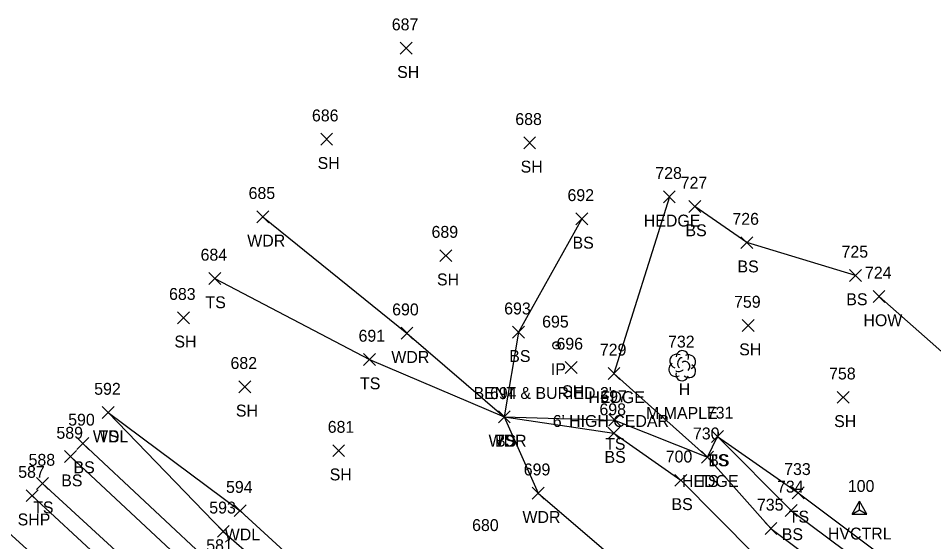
# Model space of a CAD drawing. Extents: x 1611034 to 1613847, y 761049 to 763902.
# Drawn here: x 1611761.1 to 1611914.9, y 763188 to 763276 of the extents above; entities that cross this region are included whole.
import ezdxf

# ---------------------------------------------------------------- set-up
doc = ezdxf.new("R2010")
doc.units = 0
for name, color, linetype in [('C_A', 7, 'Continuous'), ('C_I', 7, 'Continuous'), ('CPSM', 7, 'Continuous'), ('L_A', 7, 'Continuous'), ('L_C', 7, 'Continuous'), ('L_I', 7, 'Continuous'), ('L_TIC', 7, 'Continuous'), ('LAHR', 7, 'Continuous'), ('LAWA', 7, 'Continuous'), ('LBC', 7, 'Continuous'), ('LELB', 7, 'Continuous'), ('LTD', 7, 'Continuous'), ('M_A', 7, 'Continuous'), ('M_C', 7, 'Continuous'), ('M_I', 7, 'Continuous'), ('MPIR', 7, 'Continuous'), ('P_A', 7, 'Continuous'), ('P_I', 7, 'Continuous'), ('P_TIC', 7, 'Continuous'), ('PET', 7, 'Continuous'), ('PSP', 7, 'Continuous')]:
    doc.layers.add(name, color=color, linetype=linetype)

msp = doc.modelspace()

# ---------------------------------------------------------------- linework, layer by layer
at = {"layer": 'CPSM'}
for p, q in [((1611901.21, 763192.65), (1611902.46, 763194.81)), ((1611903.71, 763192.65), (1611902.46, 763194.81)), ((1611902.46, 763193.37), (1611902.46, 763194.81)), ((1611901.21, 763192.65), (1611902.46, 763193.37)), ((1611901.21, 763192.65), (1611903.71, 763192.65)), ((1611902.46, 763193.37), (1611902.46, 763193.37)), ((1611902.46, 763193.37), (1611903.71, 763192.65))]:
    msp.add_line(p, q, dxfattribs=at)
at = {"layer": 'L_TIC'}
for points in [[(1611825.26, 763269.99), (1611827.26, 763271.99)], [(1611827.26, 763269.99), (1611825.26, 763271.99)], [(1611811.9, 763254.68), (1611813.9, 763256.68)], [(1611813.9, 763254.68), (1611811.9, 763256.68)], [(1611846.02, 763254.07), (1611848.02, 763256.07)], [(1611848.02, 763254.07), (1611846.02, 763256.07)], [(1611869.5, 763245), (1611871.5, 763247)], [(1611871.5, 763245), (1611869.5, 763247)], [(1611873.77, 763243.37), (1611875.77, 763245.37)], [(1611875.77, 763243.37), (1611873.77, 763245.37)], [(1611801.19, 763241.63), (1611803.19, 763243.63)], [(1611803.19, 763241.63), (1611801.19, 763243.63)], [(1611854.79, 763241.28), (1611856.79, 763243.28)], [(1611856.79, 763241.28), (1611854.79, 763243.28)], [(1611882.51, 763237.29), (1611884.51, 763239.29)], [(1611884.51, 763237.29), (1611882.51, 763239.29)], [(1611831.95, 763235.1), (1611833.95, 763237.1)], [(1611833.95, 763235.1), (1611831.95, 763237.1)], [(1611900.8, 763231.77), (1611902.8, 763233.77)], [(1611902.8, 763231.77), (1611900.8, 763233.77)], [(1611793.12, 763231.26), (1611795.12, 763233.26)], [(1611795.12, 763231.26), (1611793.12, 763233.26)], [(1611904.74, 763228.24), (1611906.74, 763230.24)], [(1611906.74, 763228.24), (1611904.74, 763230.24)], [(1611787.82, 763224.66), (1611789.82, 763226.66)], [(1611789.82, 763224.66), (1611787.82, 763226.66)], [(1611882.75, 763223.34), (1611884.75, 763225.34)], [(1611884.75, 763223.34), (1611882.75, 763225.34)], [(1611825.4, 763222.06), (1611827.4, 763224.06)], [(1611827.4, 763222.06), (1611825.4, 763224.06)], [(1611844.15, 763222.22), (1611846.15, 763224.22)], [(1611846.15, 763222.22), (1611844.15, 763224.22)], [(1611819.1, 763217.63), (1611821.1, 763219.63)], [(1611821.1, 763217.63), (1611819.1, 763219.63)], [(1611852.99, 763216.3), (1611854.99, 763218.3)], [(1611854.99, 763216.3), (1611852.99, 763218.3)], [(1611860.19, 763215.3), (1611862.19, 763217.3)], [(1611862.19, 763215.3), (1611860.19, 763217.3)], [(1611798.15, 763213.05), (1611800.15, 763215.05)], [(1611800.15, 763213.05), (1611798.15, 763215.05)], [(1611898.71, 763211.28), (1611900.71, 763213.28)], [(1611900.71, 763211.28), (1611898.71, 763213.28)], [(1611775.19, 763208.71), (1611777.19, 763210.71)], [(1611777.19, 763208.71), (1611775.19, 763210.71)], [(1611775.19, 763208.71), (1611777.19, 763210.71)], [(1611777.19, 763208.71), (1611775.19, 763210.71)], [(1611841.76, 763207.98), (1611843.76, 763209.98)], [(1611843.76, 763207.98), (1611841.76, 763209.98)], [(1611841.76, 763207.98), (1611843.76, 763209.98)], [(1611843.76, 763207.98), (1611841.76, 763209.98)], [(1611841.76, 763207.98), (1611843.76, 763209.98)], [(1611843.76, 763207.98), (1611841.76, 763209.98)], [(1611860.3, 763207.46), (1611862.3, 763209.46)], [(1611862.3, 763207.46), (1611860.3, 763209.46)], [(1611860.16, 763205.26), (1611862.16, 763207.26)], [(1611862.16, 763205.26), (1611860.16, 763207.26)], [(1611877.59, 763204.7), (1611879.59, 763206.7)], [(1611879.59, 763204.7), (1611877.59, 763206.7)], [(1611877.59, 763204.7), (1611879.59, 763206.7)], [(1611879.59, 763204.7), (1611877.59, 763206.7)], [(1611877.59, 763204.7), (1611879.59, 763206.7)], [(1611879.59, 763204.7), (1611877.59, 763206.7)], [(1611770.91, 763203.52), (1611772.91, 763205.52)], [(1611772.91, 763203.52), (1611770.91, 763205.52)], [(1611768.85, 763201.31), (1611770.85, 763203.31)], [(1611770.85, 763201.31), (1611768.85, 763203.31)], [(1611813.92, 763202.31), (1611815.92, 763204.31)], [(1611815.92, 763202.31), (1611813.92, 763204.31)], [(1611875.92, 763201.2), (1611877.92, 763203.2)], [(1611877.92, 763201.2), (1611875.92, 763203.2)], [(1611875.92, 763201.2), (1611877.92, 763203.2)], [(1611877.92, 763201.2), (1611875.92, 763203.2)], [(1611764.16, 763196.77), (1611766.16, 763198.77)], [(1611766.16, 763196.77), (1611764.16, 763198.77)], [(1611871.42, 763197.32), (1611873.42, 763199.32)], [(1611873.42, 763197.32), (1611871.42, 763199.32)], [(1611847.45, 763195.15), (1611849.45, 763197.15)], [(1611849.45, 763195.15), (1611847.45, 763197.15)], [(1611891.17, 763195.21), (1611893.17, 763197.21)], [(1611893.17, 763195.21), (1611891.17, 763197.21)], [(1611797.35, 763192.21), (1611799.35, 763194.21)], [(1611799.35, 763192.21), (1611797.35, 763194.21)], [(1611889.96, 763192.26), (1611891.96, 763194.26)], [(1611891.96, 763192.26), (1611889.96, 763194.26)], [(1611794.53, 763188.74), (1611796.53, 763190.74)], [(1611796.53, 763188.74), (1611794.53, 763190.74)], [(1611886.58, 763189.23), (1611888.58, 763191.23)], [(1611888.58, 763189.23), (1611886.58, 763191.23)]]:
    msp.add_lwpolyline(points, dxfattribs=at)
at = {"layer": 'LAHR'}
msp.add_lwpolyline([(1611870.5, 763246), (1611861.19, 763216.3), (1611876.92, 763202.2), (1611887.58, 763190.23), (1611909.6, 763173.67), (1611924.3, 763161.79), (1611933.01, 763152.8), (1611942.84, 763146), (1611944.38, 763148.34), (1611945.72, 763149.4), (1611955.37, 763161.74), (1611966.07, 763176.23)], dxfattribs=at)
at = {"layer": 'LAWA'}
for points in [[(1611802.19, 763242.63), (1611826.4, 763223.06), (1611842.76, 763208.98), (1611848.45, 763196.15), (1611870.16, 763177.55), (1611888.93, 763166.81), (1611895.61, 763159.78), (1611907.25, 763148.44), (1611925.92, 763141.58), (1611941.9, 763130.03), (1611944.3, 763130.53), (1611953.78, 763136.1), (1611962.53, 763149.06), (1611975, 763169.4)], [(1611776.19, 763209.71), (1611798.35, 763193.21), (1611821.91, 763171.59), (1611835.23, 763154.9), (1611840.73, 763150.36), (1611854.8, 763137.66), (1611869.74, 763122.61), (1611885.36, 763108.52), (1611898.9, 763094.55), (1611920.73, 763076.3), (1611936.34, 763060.75), (1611959.95, 763037.9), (1611979.24, 763021.14), (1611992.68, 763010.08), (1612014.52, 762988.49), (1612021.56, 762990.5), (1612027.56, 763011.05)]]:
    msp.add_lwpolyline(points, dxfattribs=at)
at = {"layer": 'LBC'}
msp.add_lwpolyline([(1611905.74, 763229.24), (1611942.01, 763197.25)], dxfattribs=at)
at = {"layer": 'LELB'}
for points in [[(1611901.8, 763232.77), (1611883.51, 763238.29), (1611874.77, 763244.37)], [(1611855.79, 763242.28), (1611845.15, 763223.22), (1611842.76, 763208.98), (1611861.16, 763206.26), (1611872.42, 763198.32), (1611897.21, 763173.34), (1611919.99, 763154.68), (1611938.12, 763138.36), (1611941.9, 763130.03), (1611945.43, 763119.54), (1611962.31, 763107.12), (1611958.31, 763113.02), (1611953.96, 763122.93), (1611951.67, 763129.35), (1611946.1, 763127.17)], [(1611794.12, 763232.26), (1611820.1, 763218.63), (1611842.76, 763208.98), (1611861.3, 763208.46), (1611876.92, 763202.2), (1611878.59, 763205.7)], [(1611776.19, 763209.71), (1611795.53, 763189.74), (1611818.61, 763169.56), (1611835.23, 763154.9)], [(1612018.61, 762964.73), (1611994.45, 762990.34), (1611965, 763017.91), (1611936.07, 763051.1), (1611910.74, 763076.87), (1611888.16, 763094.11), (1611862.22, 763121.84), (1611845.65, 763138.15), (1611819.53, 763160.99), (1611794.46, 763183.41), (1611771.91, 763204.52)], [(1611878.59, 763205.7), (1611892.17, 763196.21), (1611914.99, 763179.09), (1611930.29, 763167.67), (1611942.93, 763155.25), (1611945.72, 763149.4)], [(1611878.59, 763205.7), (1611890.96, 763193.26), (1611912.74, 763176.97), (1611927.67, 763166.3), (1611941.9, 763153.84), (1611944.38, 763148.34)], [(1612017.14, 762963.27), (1611992.31, 762988.18), (1611962.87, 763016.31), (1611931.63, 763047.56), (1611908.18, 763073.24), (1611886.96, 763093.2), (1611860.29, 763119.05), (1611842.79, 763135.64), (1611817.54, 763159.12), (1611792.58, 763181.1), (1611769.85, 763202.31)], [(1612014.39, 762960.1), (1611988.81, 762984.91), (1611960.67, 763014.03), (1611928.51, 763044.56), (1611903.94, 763068.78), (1611882.15, 763089), (1611856.04, 763113.65), (1611837.67, 763131.07), (1611812.66, 763153.54), (1611788.39, 763176.44), (1611765.16, 763197.77)]]:
    msp.add_lwpolyline(points, dxfattribs=at)
at = {"layer": 'LTD'}
msp.add_line((1611872.64, 763217.65), (1611872.64, 763217.65), dxfattribs=at)
msp.add_line((1611872.64, 763217.65), (1611872.64, 763217.65), dxfattribs=at)
msp.add_arc((1611872.69, 763219.08), 1.05, 335.5272, 180.9563, dxfattribs=at)
for centre, major_axis, ratio, start_param, end_param in [((1611871.85, 763218.32), (1.21, -0.51), 0.895232, 1.570796, 4.712389), ((1611872.44, 763218.11), (-0.208, -0.792), 0.645439, 3.141593, 6.283185), ((1611873.14, 763217.48), (-0.5, 0.667), 0.989748, 3.141593, 6.283185), ((1611873.69, 763218.23), (-1.14, -0.48), 0.949671, 1.570796, 4.712389), ((1611871.56, 763216.94), (0.58, -1.04), 0.959034, 3.141593, 6.283185), ((1611872.19, 763216.9), (-0.625, -0.083), 0.423636, 0, 3.141593), ((1611873.64, 763216.82), (-1.09, 0.79), 0.841452, 1.570796, 4.712389), ((1611872.64, 763216.15), (0.26, 1.06), 0.942809, 1.570796, 4.712389)]:
    msp.add_ellipse(centre, major_axis=major_axis, ratio=ratio, start_param=start_param, end_param=end_param, dxfattribs=at)
at = {"layer": 'MPIR'}
for radius in [0.625, 0.0833]:
    msp.add_circle((1611851.53, 763221.01), radius, dxfattribs=at)
at = {"layer": 'P_TIC'}
for points in [[(1611762.42, 763194.74), (1611764.42, 763196.74)], [(1611764.42, 763194.74), (1611762.42, 763196.74)]]:
    msp.add_lwpolyline(points, dxfattribs=at)
at = {"layer": 'PET'}
msp.add_lwpolyline([(1612007.41, 762953.69), (1611981.88, 762978.72), (1611953.4, 763007), (1611921.8, 763038.1), (1611897.05, 763061.61), (1611875.73, 763082.09), (1611849.32, 763106.5), (1611830.38, 763124.18), (1611806.13, 763146.18), (1611781.49, 763169.41), (1611758.07, 763190.79)], dxfattribs=at)
at = {"layer": 'PSP'}
msp.add_lwpolyline([(1612013.06, 762958.69), (1611987.98, 762983.85), (1611959.05, 763012.61), (1611927.06, 763043.5), (1611902.53, 763067.25), (1611880.81, 763087.35), (1611854.34, 763111.86), (1611835.7, 763129.09), (1611811.01, 763152.07), (1611786.17, 763174.66), (1611763.42, 763195.74)], dxfattribs=at)

# ---------------------------------------------------------------- texts
at = {"layer": 'C_A'}
msp.add_text('HVCTRL', height=2, dxfattribs=at).set_placement((1611897.15, 763188.37))
at = {"layer": 'C_I'}
msp.add_text('100', height=2, dxfattribs=at).set_placement((1611900.5, 763196.37))
at = {"layer": 'L_A'}
for s, p in [('SH', (1611824.75, 763265.99)), ('SH', (1611811.38, 763250.68)), ('SH', (1611845.5, 763250.07)), ('HEDGE', (1611866.2, 763241)), ('BS', (1611873.21, 763239.37)), ('WDR', (1611799.55, 763237.63)), ('BS', (1611854.23, 763237.28)), ('BS', (1611881.95, 763233.29)), ('SH', (1611831.44, 763231.1)), ('TS', (1611792.53, 763227.26)), ('BS', (1611900.24, 763227.77)), ('HOW', (1611903.12, 763224.24)), ('SH', (1611787.31, 763220.66)), ('WDR', (1611823.77, 763218.06)), ('BS', (1611843.59, 763218.22)), ('SH', (1611882.24, 763219.34)), ('TS', (1611818.51, 763213.63)), ('SH', (1611852.48, 763212.3)), ('H', (1611872.08, 763212.65)), ('HEDGE', (1611856.89, 763211.3)), ('SH', (1611797.64, 763209.05)), ('SH', (1611898.2, 763207.28)), ('WDL', (1611773.61, 763204.71)), ('TS', (1611774.6, 763204.71)), ('TS', (1611841.17, 763203.98)), ('BS', (1611841.2, 763203.98)), ('WDR', (1611840.12, 763203.98)), ('TS', (1611859.71, 763203.46)), ('BS', (1611859.6, 763201.26)), ('BS', (1611770.35, 763199.52)), ('TS', (1611877, 763200.7)), ('TS', (1611877, 763200.7)), ('BS', (1611877.03, 763200.7)), ('SH', (1611813.41, 763198.31)), ('BS', (1611768.29, 763197.31)), ('HEDGE', (1611872.62, 763197.2)), ('TS', (1611875.33, 763197.2)), ('BS', (1611870.86, 763193.32)), ('TS', (1611763.57, 763192.77)), ('WDR', (1611845.81, 763191.15)), ('TS', (1611890.57, 763191.21)), ('WDL', (1611795.77, 763188.21)), ('BS', (1611889.4, 763188.26))]:
    msp.add_text(s, height=2, dxfattribs=at).set_placement(p)
at = {"layer": 'L_C'}
for s, p in [('M.MAPLE', (1611866.58, 763208.65)), ("6' HIGH CEDAR", (1611850.91, 763207.3))]:
    msp.add_text(s, height=2, dxfattribs=at).set_placement(p)
at = {"layer": 'L_I'}
for s, p in [('687', (1611823.85, 763273.99)), ('686', (1611810.43, 763258.68)), ('688', (1611844.61, 763258.07)), ('728', (1611868.14, 763249)), ('727', (1611872.4, 763247.37)), ('685', (1611799.78, 763245.63)), ('692', (1611853.38, 763245.28)), ('726', (1611881.1, 763241.29)), ('689', (1611830.53, 763239.1)), ('684', (1611791.71, 763235.26)), ('725', (1611899.44, 763235.77)), ('724', (1611903.38, 763232.24)), ('683', (1611786.41, 763228.66)), ('759', (1611881.38, 763227.34)), ('690', (1611823.91, 763226.06)), ('693', (1611842.74, 763226.22)), ('691', (1611818.26, 763221.63)), ('696', (1611851.53, 763220.3)), ('732', (1611870.28, 763220.65)), ('729', (1611858.82, 763219.3)), ('682', (1611796.74, 763217.05)), ('758', (1611897.35, 763215.28)), ('592', (1611773.83, 763212.71)), ('592', (1611773.83, 763212.71)), ('694', (1611840.35, 763211.98)), ('694', (1611840.35, 763211.98)), ('694', (1611840.35, 763211.98)), ('697', (1611858.89, 763211.46)), ('698', (1611858.75, 763209.26)), ('731', (1611876.8, 763208.7)), ('731', (1611876.8, 763208.7)), ('731', (1611876.8, 763208.7)), ('590', (1611769.46, 763207.52)), ('681', (1611813.08, 763206.31)), ('589', (1611767.48, 763205.31)), ('730', (1611874.47, 763205.2)), ('730', (1611874.47, 763205.2)), ('700', (1611869.89, 763201.32)), ('588', (1611762.8, 763200.77)), ('699', (1611846.03, 763199.15)), ('733', (1611889.8, 763199.21)), ('594', (1611795.99, 763196.21)), ('734', (1611888.6, 763196.26)), ('735', (1611885.22, 763193.23)), ('593', (1611793.17, 763192.74)), ('680', (1611837.35, 763189.79)), ('581', (1611792.66, 763186.41))]:
    msp.add_text(s, height=2, dxfattribs=at).set_placement(p)
at = {"layer": 'M_A'}
msp.add_text('IP', height=2, dxfattribs=at).set_placement((1611850.58, 763216.01))
at = {"layer": 'M_C'}
msp.add_text("BENT & BURIED 2'", height=2, dxfattribs=at).set_placement((1611837.59, 763212.01))
at = {"layer": 'M_I'}
msp.add_text('695', height=2, dxfattribs=at).set_placement((1611849.12, 763224.01))
at = {"layer": 'P_A'}
msp.add_text('SHP', height=2, dxfattribs=at).set_placement((1611760.96, 763190.74))
at = {"layer": 'P_I'}
msp.add_text('587', height=2, dxfattribs=at).set_placement((1611761.06, 763198.74))

doc.saveas('drawing.dxf')
